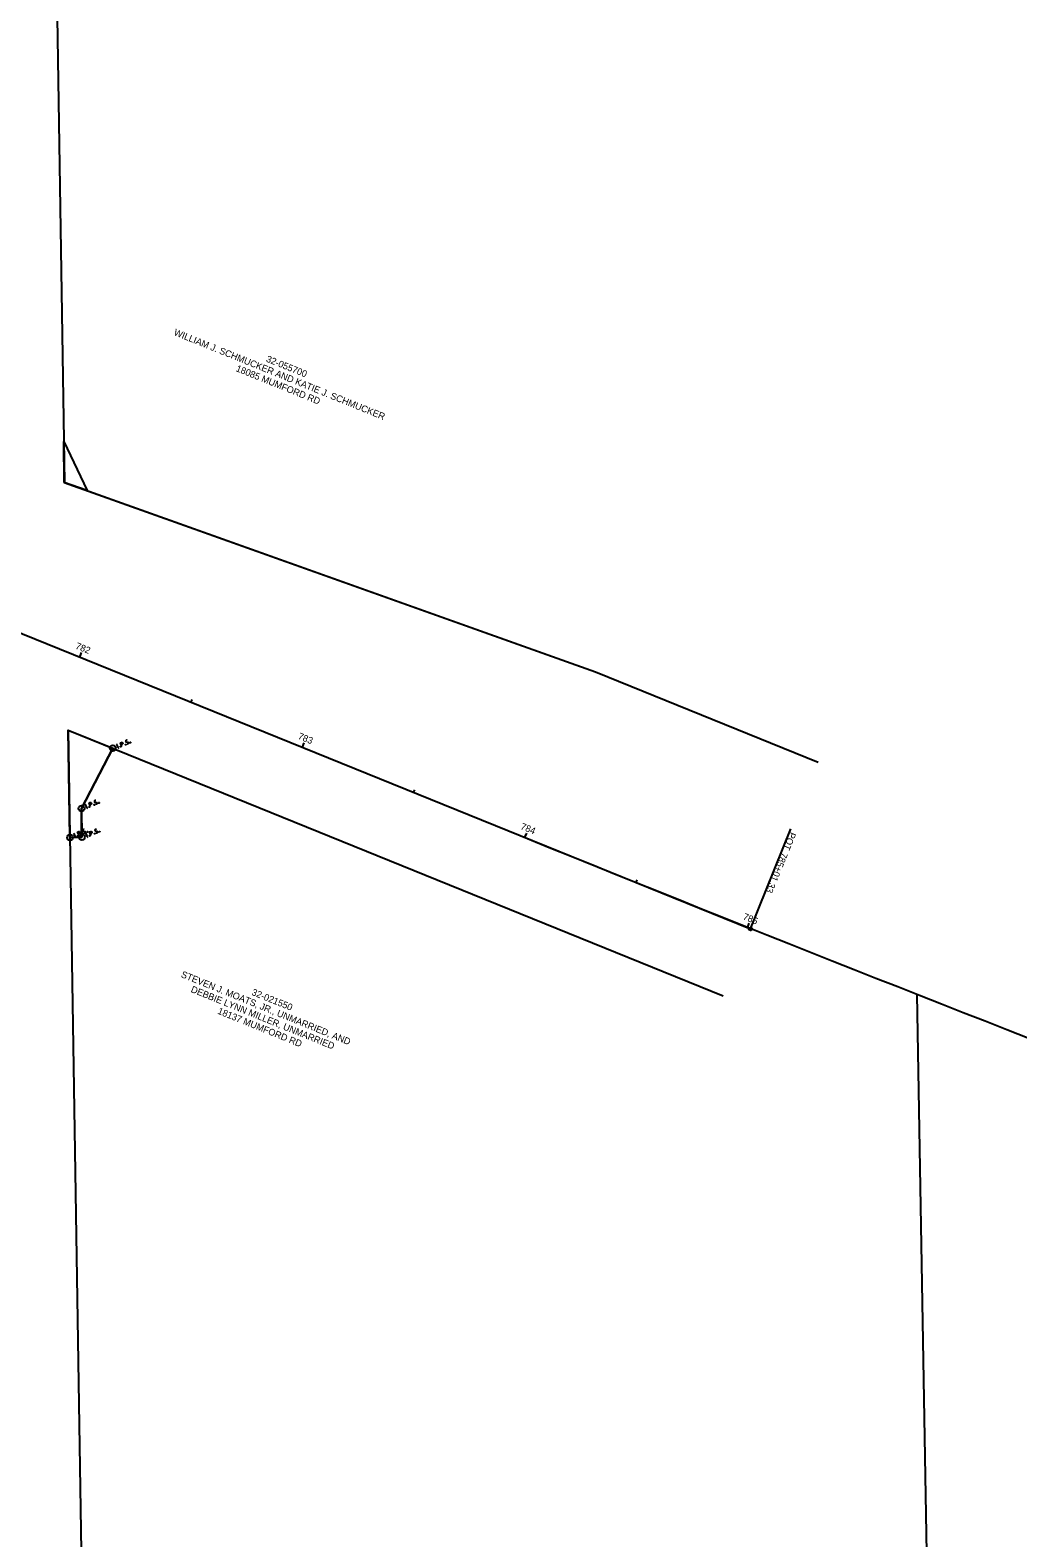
# Model space of a CAD drawing. Extents: x 2345526 to 2352728, y 625359 to 628213.
# Drawn here: x 2350675 to 2351086, y 625748 to 626376 of the extents above; entities that cross this region are included whole.
import ezdxf

# ---------------------------------------------------------------- set-up
doc = ezdxf.new("R2010")
doc.units = 0
for name, color, linetype in [('DR_P_Ditch', 7, 'Continuous'), ('DR_P_Headwall', 7, 'Continuous'), ('DR_X_Cells', 7, 'Continuous'), ('DR_X_Ditch', 7, 'Continuous'), ('DR_X_GenericNode', 7, 'Continuous'), ('DR_X_Storm_Sewer', 7, 'Continuous'), ('GE_P_Alignment', 7, 'Continuous'), ('GK_Drainage_Nodes', 7, 'Continuous'), ('PF_P_Grade_Line', 7, 'Continuous'), ('PF_X_Ground_Line', 7, 'Continuous'), ('RW_P_Esmt_SH', 7, 'Continuous'), ('RW_P_Esmt_TMP', 7, 'Continuous'), ('RW_X_Text', 7, 'Continuous'), ('SC_Scratch1', 7, 'Continuous'), ('SN_X_Private', 7, 'Continuous'), ('VG_X_Tree_Line_Rt', 7, 'Continuous')]:
    doc.layers.add(name, color=color, linetype=linetype)

msp = doc.modelspace()

# ---------------------------------------------------------------- linework, layer by layer
at = {"layer": 'DR_P_Ditch'}
msp.add_line((2348868.68, 626855.7), (2350975.06, 626001.36), dxfattribs=at)
at = {"layer": 'DR_P_Headwall'}
msp.add_line((2350973.83, 626001.86), (2350974.28, 626002.97), dxfattribs=at)
at = {"layer": 'DR_X_Cells'}
msp.add_line((2350975.06, 626001.36), (2350991.97, 626043.06), dxfattribs=at)
msp.add_circle((2350975.06, 626001.36), 0.6, dxfattribs=at)
at = {"layer": 'DR_X_Ditch'}
msp.add_line((2350975.06, 626001.36), (2350991.97, 626043.06), dxfattribs=at)
msp.add_circle((2350975.06, 626001.36), 0.6, dxfattribs=at)
at = {"layer": 'DR_X_GenericNode'}
for p, q in [((2350677.91, 626921.36), (2350689.4, 626187.36)), ((2350689.35, 626187.37), (2350910.58, 626108.45)), ((2350689.4, 626187.36), (2350910.58, 626108.45)), ((2350910.58, 626108.45), (2351003.25, 626070.86)), ((2350910.58, 626108.45), (2351003.25, 626070.86)), ((2350691.02, 626084.19), (2350963.78, 625973.56)), ((2350691.02, 626084.19), (2350702.35, 625360.42))]:
    msp.add_line(p, q, dxfattribs=at)
at = {"layer": 'DR_X_Storm_Sewer'}
msp.add_line((2351050.65, 625617.48), (2351044.6, 625974.12), dxfattribs=at)
msp.add_arc((2357342.83, 641967.55), 17188.88, 247.922783, 252.089433, dxfattribs=at)
at = {"layer": 'GE_P_Alignment'}
msp.add_line((2350975.06, 626001.36), (2350991.97, 626043.06), dxfattribs=at)
msp.add_circle((2350975.06, 626001.36), 0.6, dxfattribs=at)
at = {"layer": 'GK_Drainage_Nodes'}
for p, q in [((2350695.82, 626114.62), (2350696.28, 626115.73)), ((2350788.49, 626077.03), (2350788.94, 626078.15)), ((2350881.16, 626039.45), (2350881.61, 626040.56)), ((2350973.83, 626001.86), (2350974.58, 626003.72))]:
    msp.add_line(p, q, dxfattribs=at)
at = {"layer": 'PF_P_Grade_Line'}
for p, q in [((2350689.09, 626204.37), (2350689.18, 626204.34)), ((2350689.12, 626204.31), (2350689.16, 626204.4)), ((2350689.31, 626187.39), (2350689.4, 626187.36)), ((2350689.34, 626187.33), (2350689.37, 626187.42)), ((2350698.78, 626184.02), (2350698.86, 626183.98)), ((2350698.8, 626183.96), (2350698.84, 626184.04)), ((2350690.97, 626084.21), (2350691.06, 626084.18)), ((2350691, 626084.15), (2350691.04, 626084.24)), ((2350709.53, 626076.69), (2350709.61, 626076.65)), ((2350709.55, 626076.63), (2350709.59, 626076.71)), ((2350696.49, 626051.6), (2350696.57, 626051.56)), ((2350696.51, 626051.54), (2350696.55, 626051.62)), ((2350691.67, 626039.52), (2350691.76, 626039.48)), ((2350691.7, 626039.46), (2350691.74, 626039.55)), ((2350696.67, 626039.6), (2350696.76, 626039.56)), ((2350696.7, 626039.54), (2350696.74, 626039.62))]:
    msp.add_line(p, q, dxfattribs=at)
at = {"layer": 'PF_X_Ground_Line'}
for points in [[(2350715.54, 626079.94), (2350715.51, 626079.96), (2350715.47, 626079.97), (2350715.36, 626079.96), (2350715.24, 626079.94), (2350715.16, 626079.9), (2350715.13, 626079.89), (2350715.01, 626079.8), (2350714.93, 626079.68), (2350714.9, 626079.56), (2350714.91, 626079.46), (2350714.94, 626079.39), (2350715, 626079.31), (2350715.12, 626079.26), (2350715.82, 626079.15), (2350715.89, 626079.12), (2350715.93, 626079.08), (2350715.98, 626079.02), (2350716.01, 626078.95), (2350716.03, 626078.88), (2350716.04, 626078.83), (2350716.05, 626078.76), (2350716.05, 626078.71), (2350716.04, 626078.66), (2350716.02, 626078.62), (2350716, 626078.58), (2350715.97, 626078.54), (2350715.95, 626078.51), (2350715.86, 626078.46), (2350715.72, 626078.4), (2350715.62, 626078.39), (2350715.45, 626078.41), (2350715.34, 626078.45)], [(2350711.12, 626078.2), (2350711.44, 626078.33)], [(2350711.9, 626076.79), (2350711.28, 626078.26)], [(2350711.74, 626076.72), (2350712.06, 626076.86)], [(2350712.7, 626077.36), (2350712.75, 626077.38), (2350712.79, 626077.37), (2350712.84, 626077.34), (2350712.87, 626077.28), (2350712.86, 626077.22), (2350712.84, 626077.19), (2350712.79, 626077.16), (2350712.74, 626077.17), (2350712.69, 626077.21), (2350712.67, 626077.27), (2350712.68, 626077.32), (2350712.7, 626077.36)], [(2350713.34, 626077.4), (2350712.72, 626078.87), (2350713.21, 626079.08), (2350713.26, 626079.09), (2350713.34, 626079.1), (2350713.38, 626079.09), (2350713.42, 626079.08), (2350713.49, 626079.03), (2350713.54, 626078.99), (2350713.6, 626078.91), (2350713.66, 626078.77), (2350713.67, 626078.72), (2350713.68, 626078.64), (2350713.68, 626078.54), (2350713.65, 626078.49), (2350713.63, 626078.45), (2350713.59, 626078.41), (2350713.51, 626078.36), (2350713.02, 626078.15)], [(2350714.77, 626078.24), (2350714.82, 626078.26), (2350714.86, 626078.25), (2350714.91, 626078.21), (2350714.94, 626078.16), (2350714.93, 626078.1), (2350714.91, 626078.06), (2350714.86, 626078.04), (2350714.82, 626078.05), (2350714.77, 626078.08), (2350714.74, 626078.14), (2350714.75, 626078.2), (2350714.77, 626078.24)], [(2350716.78, 626079.09), (2350716.83, 626079.11), (2350716.87, 626079.1), (2350716.92, 626079.06), (2350716.95, 626079.01), (2350716.94, 626078.95), (2350716.92, 626078.91), (2350716.87, 626078.89), (2350716.83, 626078.9), (2350716.78, 626078.93), (2350716.75, 626078.99), (2350716.76, 626079.05), (2350716.78, 626079.09)], [(2350702.5, 626054.85), (2350702.47, 626054.86), (2350702.43, 626054.87), (2350702.32, 626054.87), (2350702.2, 626054.85), (2350702.12, 626054.81), (2350702.09, 626054.8), (2350701.97, 626054.71), (2350701.89, 626054.59), (2350701.86, 626054.47), (2350701.87, 626054.37), (2350701.9, 626054.3), (2350701.96, 626054.21), (2350702.08, 626054.17), (2350702.79, 626054.06), (2350702.86, 626054.03), (2350702.9, 626053.99), (2350702.95, 626053.93), (2350702.97, 626053.86), (2350702.99, 626053.79), (2350703, 626053.74), (2350703.01, 626053.67), (2350703.01, 626053.62), (2350703, 626053.57), (2350702.99, 626053.52), (2350702.96, 626053.49), (2350702.93, 626053.45), (2350702.91, 626053.42), (2350702.82, 626053.37), (2350702.68, 626053.31), (2350702.58, 626053.3), (2350702.41, 626053.32), (2350702.3, 626053.36)], [(2350698.08, 626053.1), (2350698.4, 626053.24)], [(2350698.86, 626051.7), (2350698.24, 626053.17)], [(2350698.7, 626051.63), (2350699.03, 626051.77)], [(2350699.66, 626052.27), (2350699.71, 626052.29), (2350699.75, 626052.28), (2350699.8, 626052.25), (2350699.83, 626052.19), (2350699.82, 626052.13), (2350699.8, 626052.09), (2350699.75, 626052.07), (2350699.71, 626052.08), (2350699.66, 626052.12), (2350699.63, 626052.17), (2350699.64, 626052.23), (2350699.66, 626052.27)], [(2350700.3, 626052.31), (2350699.68, 626053.78), (2350700.17, 626053.99), (2350700.22, 626054), (2350700.3, 626054), (2350700.35, 626053.99), (2350700.39, 626053.98), (2350700.45, 626053.94), (2350700.51, 626053.9), (2350700.57, 626053.81), (2350700.62, 626053.67), (2350700.63, 626053.62), (2350700.64, 626053.55), (2350700.64, 626053.45), (2350700.61, 626053.4), (2350700.59, 626053.36), (2350700.55, 626053.31), (2350700.47, 626053.27), (2350699.99, 626053.06)], [(2350701.73, 626053.15), (2350701.78, 626053.17), (2350701.82, 626053.16), (2350701.87, 626053.12), (2350701.9, 626053.07), (2350701.89, 626053.01), (2350701.87, 626052.97), (2350701.82, 626052.95), (2350701.78, 626052.96), (2350701.73, 626052.99), (2350701.7, 626053.05), (2350701.71, 626053.11), (2350701.73, 626053.15)], [(2350703.74, 626054), (2350703.79, 626054.02), (2350703.83, 626054.01), (2350703.88, 626053.97), (2350703.91, 626053.92), (2350703.9, 626053.86), (2350703.88, 626053.82), (2350703.83, 626053.8), (2350703.79, 626053.81), (2350703.74, 626053.84), (2350703.71, 626053.9), (2350703.72, 626053.96), (2350703.74, 626054)], [(2350695.49, 626040.23), (2350694.87, 626041.71), (2350695.36, 626041.91), (2350695.41, 626041.92), (2350695.49, 626041.93), (2350695.53, 626041.92), (2350695.57, 626041.91), (2350695.64, 626041.87), (2350695.69, 626041.82), (2350695.75, 626041.74), (2350695.81, 626041.6), (2350695.82, 626041.55), (2350695.83, 626041.47), (2350695.82, 626041.37), (2350695.8, 626041.32), (2350695.78, 626041.28), (2350695.74, 626041.24), (2350695.66, 626041.19), (2350695.17, 626040.99)], [(2350697.69, 626042.77), (2350697.66, 626042.79), (2350697.61, 626042.8), (2350697.51, 626042.79), (2350697.39, 626042.77), (2350697.31, 626042.74), (2350697.28, 626042.72), (2350697.16, 626042.63), (2350697.08, 626042.52), (2350697.04, 626042.39), (2350697.06, 626042.29), (2350697.09, 626042.22), (2350697.15, 626042.14), (2350697.27, 626042.09), (2350697.97, 626041.98), (2350698.04, 626041.95), (2350698.08, 626041.92), (2350698.13, 626041.85), (2350698.16, 626041.79), (2350698.18, 626041.71), (2350698.19, 626041.66), (2350698.2, 626041.59), (2350698.2, 626041.54), (2350698.19, 626041.5), (2350698.17, 626041.45), (2350698.15, 626041.41), (2350698.12, 626041.37), (2350698.1, 626041.35), (2350698.01, 626041.3), (2350697.87, 626041.24), (2350697.77, 626041.22), (2350697.6, 626041.25), (2350697.49, 626041.28)], [(2350698.93, 626041.92), (2350698.98, 626041.94), (2350699.02, 626041.93), (2350699.07, 626041.9), (2350699.1, 626041.84), (2350699.09, 626041.78), (2350699.07, 626041.74), (2350699.02, 626041.72), (2350698.98, 626041.73), (2350698.93, 626041.77), (2350698.9, 626041.82), (2350698.91, 626041.88), (2350698.93, 626041.92)], [(2350700.49, 626040.31), (2350699.87, 626041.78), (2350700.36, 626041.99), (2350700.41, 626042), (2350700.49, 626042.01), (2350700.53, 626042), (2350700.57, 626041.99), (2350700.64, 626041.94), (2350700.69, 626041.9), (2350700.75, 626041.82), (2350700.81, 626041.68), (2350700.82, 626041.63), (2350700.83, 626041.55), (2350700.82, 626041.45), (2350700.8, 626041.4), (2350700.78, 626041.36), (2350700.74, 626041.32), (2350700.66, 626041.27), (2350700.17, 626041.06)], [(2350702.68, 626042.85), (2350702.65, 626042.87), (2350702.61, 626042.88), (2350702.51, 626042.87), (2350702.39, 626042.85), (2350702.31, 626042.81), (2350702.28, 626042.8), (2350702.16, 626042.71), (2350702.08, 626042.59), (2350702.04, 626042.47), (2350702.06, 626042.37), (2350702.09, 626042.3), (2350702.15, 626042.22), (2350702.27, 626042.17), (2350702.97, 626042.06), (2350703.04, 626042.03), (2350703.08, 626041.99), (2350703.13, 626041.93), (2350703.16, 626041.86), (2350703.18, 626041.79), (2350703.19, 626041.74), (2350703.2, 626041.67), (2350703.19, 626041.62), (2350703.19, 626041.57), (2350703.17, 626041.53), (2350703.15, 626041.49), (2350703.12, 626041.45), (2350703.1, 626041.43), (2350703.01, 626041.37), (2350702.87, 626041.31), (2350702.77, 626041.3), (2350702.6, 626041.32), (2350702.49, 626041.36)], [(2350703.93, 626042), (2350703.98, 626042.02), (2350704.02, 626042.01), (2350704.07, 626041.97), (2350704.1, 626041.92), (2350704.09, 626041.86), (2350704.07, 626041.82), (2350704.02, 626041.8), (2350703.97, 626041.81), (2350703.92, 626041.84), (2350703.9, 626041.9), (2350703.91, 626041.96), (2350703.93, 626042)], [(2350693.27, 626041.03), (2350693.59, 626041.16)], [(2350694.05, 626039.62), (2350693.43, 626041.1)], [(2350693.89, 626039.55), (2350694.21, 626039.69)], [(2350694.85, 626040.19), (2350694.9, 626040.21), (2350694.94, 626040.2), (2350694.99, 626040.17), (2350695.02, 626040.11), (2350695.01, 626040.05), (2350694.99, 626040.02), (2350694.93, 626040), (2350694.89, 626040.01), (2350694.84, 626040.04), (2350694.82, 626040.1), (2350694.83, 626040.16), (2350694.85, 626040.19)], [(2350696.92, 626041.07), (2350696.97, 626041.09), (2350697.01, 626041.08), (2350697.06, 626041.05), (2350697.09, 626040.99), (2350697.08, 626040.93), (2350697.06, 626040.89), (2350697.01, 626040.87), (2350696.97, 626040.88), (2350696.92, 626040.92), (2350696.89, 626040.97), (2350696.9, 626041.03), (2350696.92, 626041.07)], [(2350698.26, 626041.11), (2350698.59, 626041.24)], [(2350699.05, 626039.7), (2350698.43, 626041.17)], [(2350698.89, 626039.63), (2350699.21, 626039.77)], [(2350699.85, 626040.27), (2350699.9, 626040.29), (2350699.94, 626040.28), (2350699.99, 626040.25), (2350700.02, 626040.19), (2350700.01, 626040.13), (2350699.98, 626040.1), (2350699.93, 626040.07), (2350699.89, 626040.08), (2350699.84, 626040.12), (2350699.82, 626040.18), (2350699.83, 626040.24), (2350699.85, 626040.27)], [(2350701.92, 626041.15), (2350701.97, 626041.17), (2350702.01, 626041.16), (2350702.06, 626041.12), (2350702.09, 626041.07), (2350702.08, 626041.01), (2350702.06, 626040.97), (2350702, 626040.95), (2350701.96, 626040.96), (2350701.91, 626040.99), (2350701.89, 626041.05), (2350701.9, 626041.11), (2350701.92, 626041.15)]]:
    msp.add_lwpolyline(points, dxfattribs=at)
for centre in [(2350709.57, 626076.67), (2350696.53, 626051.58), (2350691.72, 626039.5), (2350696.72, 626039.58)]:
    msp.add_circle(centre, 1.2, dxfattribs=at)
at = {"layer": 'RW_P_Esmt_SH'}
for p, q in [((2350696.53, 626051.58), (2350709.57, 626076.67)), ((2350696.5, 626039.44), (2350696.53, 626051.58)), ((2350691.72, 626039.5), (2350696.72, 626039.58))]:
    msp.add_line(p, q, dxfattribs=at)
at = {"layer": 'RW_P_Esmt_TMP'}
msp.add_line((2350689.14, 626204.35), (2350698.82, 626184), dxfattribs=at)
msp.add_line((2350689.14, 626204.35), (2350698.82, 626184), dxfattribs=at)
at = {"layer": 'SC_Scratch1'}
for p, q in [((2350695.82, 626114.62), (2350696.58, 626116.47)), ((2350742.16, 626095.83), (2350742.61, 626096.94)), ((2350788.49, 626077.03), (2350789.24, 626078.89)), ((2350834.83, 626058.24), (2350835.28, 626059.35)), ((2350881.16, 626039.45), (2350881.91, 626041.3)), ((2350927.49, 626020.65), (2350927.94, 626021.77)), ((2350973.83, 626001.86), (2350974.58, 626003.72))]:
    msp.add_line(p, q, dxfattribs=at)
at = {"layer": 'SN_X_Private'}
for p, q in [((2350691.72, 626039.5), (2350691.02, 626084.19)), ((2350691.02, 626084.19), (2350709.57, 626076.67)), ((2350709.57, 626076.67), (2350696.53, 626051.58)), ((2350696.53, 626051.58), (2350696.72, 626039.58)), ((2350696.72, 626039.58), (2350691.72, 626039.5))]:
    msp.add_line(p, q, dxfattribs=at)
at = {"layer": 'VG_X_Tree_Line_Rt'}
for p, q in [((2350689.35, 626187.37), (2350689.14, 626204.35)), ((2350689.14, 626204.35), (2350698.82, 626184)), ((2350698.82, 626184), (2350689.35, 626187.37))]:
    msp.add_line(p, q, dxfattribs=at)

# ---------------------------------------------------------------- texts
at = {"layer": 'DR_X_Cells'}
for s, p in [('POT', (2350991.59, 626041.99)), ('785+01.33', (2350988.16, 626033.53))]:
    msp.add_text(s, height=2.8, rotation=247.92278, dxfattribs=at).set_placement(p)
at = {"layer": 'DR_X_Ditch'}
for s, p in [('POT', (2350991.59, 626041.99)), ('785+01.33', (2350988.16, 626033.53))]:
    msp.add_text(s, height=2.8, rotation=247.92278, dxfattribs=at).set_placement(p)
at = {"layer": 'GE_P_Alignment'}
for s, p in [('POT', (2350991.59, 626041.99)), ('785+01.33', (2350988.16, 626033.53))]:
    msp.add_text(s, height=2.8, rotation=247.92278, dxfattribs=at).set_placement(p)
at = {"layer": 'GK_Drainage_Nodes'}
msp.add_text('785', height=2.8, rotation=337.92278, dxfattribs=at).set_placement((2350971.73, 626005.46))
at = {"layer": 'RW_X_Text'}
for s, p in [('WILLIAM J. SCHMUCKER AND KATIE J. SCHMUCKER', (2350734.71, 626248.82)), ('32-055700', (2350773.15, 626237.76)), ('18085 MUMFORD RD', (2350760.56, 626233.8)), ('STEVEN J. MOATS, JR., UNMARRIED, AND', (2350737.71, 625981.37)), ('DEBBIE LYNN MILLER, UNMARRIED', (2350741.8, 625975.17)), ('32-021550', (2350767.12, 625973.97)), ('18137 MUMFORD RD', (2350752.95, 625966.12))]:
    msp.add_text(s, height=2.8, rotation=337.92278, dxfattribs=at).set_placement(p)
at = {"layer": 'SC_Scratch1'}
for s, p in [('782', (2350693.75, 626118.21)), ('783', (2350786.42, 626080.62)), ('784', (2350879.12, 626043.03)), ('785', (2350971.73, 626005.46))]:
    msp.add_text(s, height=2.8, rotation=337.92278, dxfattribs=at).set_placement(p)

doc.saveas('drawing.dxf')
